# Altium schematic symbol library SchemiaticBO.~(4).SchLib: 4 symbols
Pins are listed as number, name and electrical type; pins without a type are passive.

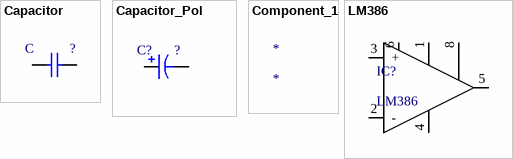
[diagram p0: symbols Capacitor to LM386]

## Capacitor
designator C  (value not drawn)
footprint SMD_0603_BO
footprint SMD_1206_BO
pins: 1, 2

## Capacitor_Pol
designator C?  (value not drawn)
footprint Panasonic_K16_BO
footprint CAP_POL_s16x25 (Raster 7.5)
footprint CAP_POL_s10x20 (Raster 5)
footprint CAP_POL_s10x16 (Raster 5)
footprint CAP_POL_s6.3x11 (Raster 2.5)
footprint CAP_POL_s5x11 (Raster 2)
footprint CAP_POL_SMD_8.5x8.5x10.7
footprint CAP_POL_SMD_6.8x6.8x8
footprint CAP_POL_SMD_6.8x6.8x6
footprint CAP_POL_SMD_4.5x4.5x6
pins: 1, 2

## Component_1
designator *

## LM386
designator IC?
footprint SO8_BO
pins: 1, 2 -, 3 +, 4, 5, 6, 8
